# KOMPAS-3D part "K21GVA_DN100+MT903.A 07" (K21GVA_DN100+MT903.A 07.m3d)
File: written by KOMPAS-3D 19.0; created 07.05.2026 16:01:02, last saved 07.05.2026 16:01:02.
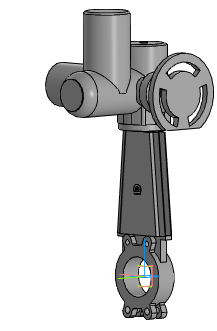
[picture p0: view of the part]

Document properties: Автор: Энергия; Полное имя файла: ..\K21GVA_DN50-DN1000+MT903.A\K21GVA_DN100+MT903.A 07.a3d

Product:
- Part/product: K21GVA_DN100+MT903.A 07
    Масса: 75.6853

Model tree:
1. Операция без истории:1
